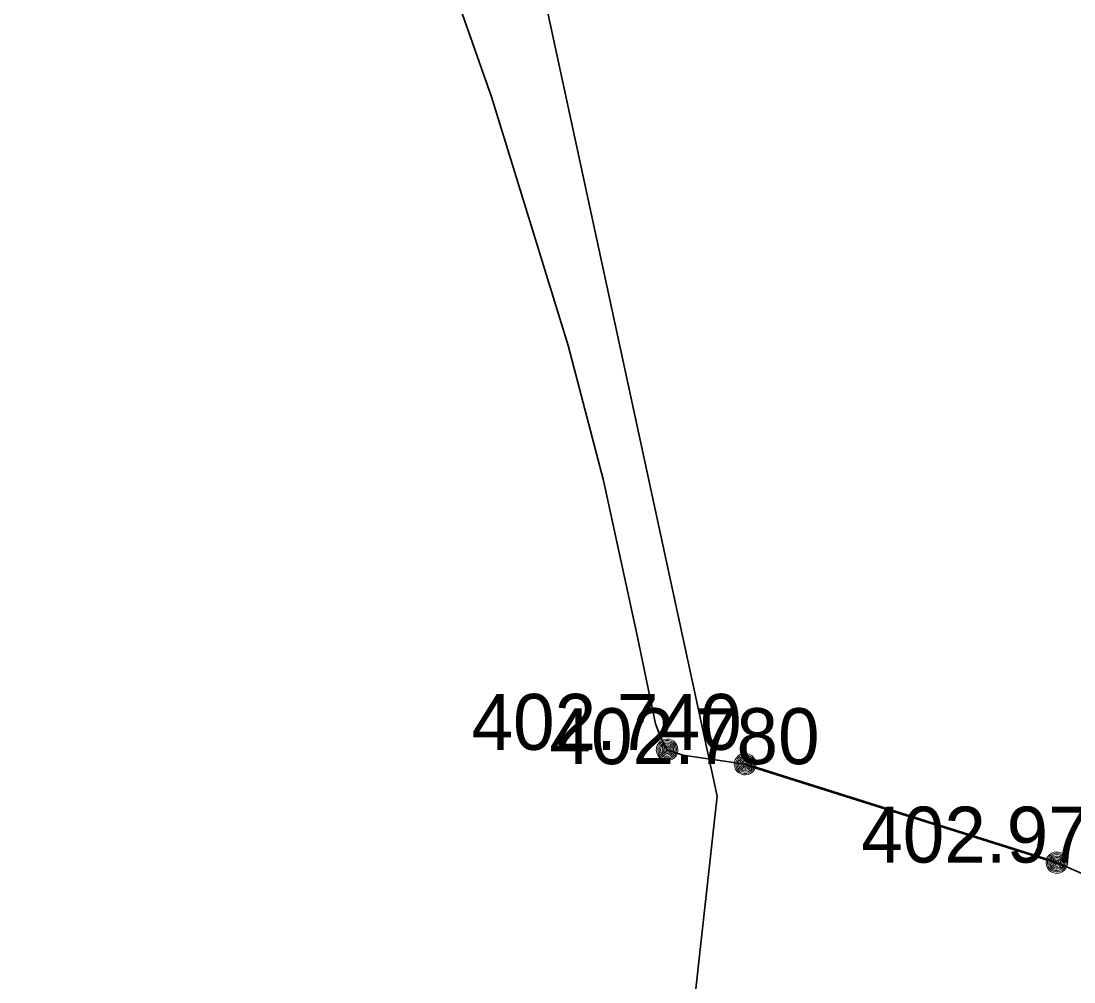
# Model space of a CAD drawing. Extents: x -873619 to -867639, y -1015082 to -1012326.
# Drawn here: x -867993.66 to -867971.06, y -1012799.51 to -1012778.89 of the extents above; entities that cross this region are included whole.
import ezdxf

# ---------------------------------------------------------------- set-up
doc = ezdxf.new("R2010")
doc.units = 0
doc.header["$LTSCALE"] = 0.44
for name, color, linetype, lineweight in [('1', 7, 'Continuous', 13), ('21', 7, 'Continuous', 35), ('26', 7, 'Continuous', 53)]:
    doc.layers.add(name, color=color, linetype=linetype, lineweight=lineweight)

msp = doc.modelspace()

# ---------------------------------------------------------------- linework, layer by layer
at = {"layer": '1', "lineweight": 35}
msp.add_lwpolyline([(-867974.611, -1012725.697), (-867976.949, -1012730.385), (-867980.624, -1012763.205), (-867983.112, -1012775.195), (-867978.719, -1012795.525), (-867979.823, -1012805.464), (-867997.768, -1012829.005), (-868011.042, -1012836.499), (-868058.95, -1012844.4), (-868077.43, -1012833.46), (-868085.171, -1012827.86)], dxfattribs=at)
at = {"layer": '1'}
for points in [[(-867979.561, -1012794.528), (-867979.568, -1012794.476), (-867979.585, -1012794.426), (-867979.614, -1012794.382), (-867979.651, -1012794.345), (-867979.696, -1012794.318), (-867979.745, -1012794.301), (-867979.799, -1012794.297), (-867979.85, -1012794.304), (-867979.899, -1012794.323), (-867979.943, -1012794.352), (-867979.978, -1012794.391), (-867980.005, -1012794.436), (-867980.021, -1012794.487), (-867980.024, -1012794.539), (-867980.016, -1012794.591), (-867979.995, -1012794.64), (-867979.965, -1012794.683), (-867979.926, -1012794.717), (-867979.88, -1012794.743), (-867979.828, -1012794.757), (-867979.776, -1012794.759), (-867979.725, -1012794.749), (-867979.676, -1012794.728), (-867979.634, -1012794.697), (-867979.6, -1012794.656), (-867979.576, -1012794.61), (-867979.563, -1012794.559)], [(-867979.592, -1012794.528), (-867979.598, -1012794.479), (-867979.615, -1012794.433), (-867979.642, -1012794.393), (-867979.679, -1012794.361), (-867979.723, -1012794.339), (-867979.772, -1012794.328), (-867979.821, -1012794.328), (-867979.867, -1012794.341), (-867979.911, -1012794.365), (-867979.946, -1012794.398), (-867979.973, -1012794.439), (-867979.99, -1012794.486), (-867979.994, -1012794.535), (-867979.987, -1012794.583), (-867979.968, -1012794.628), (-867979.938, -1012794.668), (-867979.899, -1012794.699), (-867979.855, -1012794.719), (-867979.808, -1012794.729), (-867979.759, -1012794.727), (-867979.712, -1012794.712), (-867979.669, -1012794.687), (-867979.634, -1012794.653), (-867979.608, -1012794.611), (-867979.595, -1012794.564)], [(-867979.622, -1012794.528), (-867979.627, -1012794.483), (-867979.644, -1012794.441), (-867979.673, -1012794.406), (-867979.708, -1012794.379), (-867979.75, -1012794.362), (-867979.796, -1012794.357), (-867979.84, -1012794.363), (-867979.882, -1012794.382), (-867979.916, -1012794.41), (-867979.943, -1012794.447), (-867979.96, -1012794.489), (-867979.963, -1012794.534), (-867979.956, -1012794.579), (-867979.938, -1012794.62), (-867979.909, -1012794.654), (-867979.872, -1012794.68), (-867979.828, -1012794.696), (-867979.784, -1012794.699), (-867979.739, -1012794.691), (-867979.698, -1012794.671), (-867979.664, -1012794.642), (-867979.639, -1012794.604), (-867979.625, -1012794.561)], [(-867979.652, -1012794.528), (-867979.656, -1012794.487), (-867979.674, -1012794.45), (-867979.701, -1012794.419), (-867979.737, -1012794.398), (-867979.777, -1012794.387), (-867979.818, -1012794.389), (-867979.857, -1012794.402), (-867979.891, -1012794.426), (-867979.916, -1012794.458), (-867979.931, -1012794.496), (-867979.933, -1012794.537), (-867979.926, -1012794.577), (-867979.906, -1012794.613), (-867979.877, -1012794.642), (-867979.84, -1012794.661), (-867979.799, -1012794.669), (-867979.759, -1012794.665), (-867979.72, -1012794.65), (-867979.688, -1012794.624), (-867979.666, -1012794.59), (-867979.652, -1012794.551)], [(-867979.681, -1012794.528), (-867979.686, -1012794.492), (-867979.705, -1012794.46), (-867979.73, -1012794.435), (-867979.764, -1012794.42), (-867979.801, -1012794.417), (-867979.835, -1012794.425), (-867979.867, -1012794.445), (-867979.889, -1012794.473), (-867979.902, -1012794.507), (-867979.902, -1012794.544), (-867979.892, -1012794.579), (-867979.87, -1012794.608), (-867979.84, -1012794.629), (-867979.806, -1012794.639), (-867979.769, -1012794.637), (-867979.735, -1012794.623), (-867979.708, -1012794.6), (-867979.688, -1012794.568), (-867979.681, -1012794.533)], [(-867979.712, -1012794.528), (-867979.717, -1012794.497), (-867979.733, -1012794.471), (-867979.759, -1012794.454), (-867979.789, -1012794.447), (-867979.821, -1012794.451), (-867979.848, -1012794.468), (-867979.865, -1012794.492), (-867979.874, -1012794.523), (-867979.87, -1012794.553), (-867979.855, -1012794.581), (-867979.83, -1012794.6), (-867979.801, -1012794.609), (-867979.769, -1012794.606), (-867979.742, -1012794.592), (-867979.722, -1012794.568), (-867979.712, -1012794.539)], [(-867979.742, -1012794.528), (-867979.747, -1012794.504), (-867979.764, -1012794.486), (-867979.786, -1012794.477), (-867979.811, -1012794.48), (-867979.831, -1012794.494), (-867979.843, -1012794.516), (-867979.843, -1012794.541), (-867979.83, -1012794.562), (-867979.811, -1012794.576), (-867979.786, -1012794.579), (-867979.762, -1012794.57), (-867979.747, -1012794.552)], [(-867979.772, -1012794.528), (-867979.777, -1012794.513), (-867979.791, -1012794.507), (-867979.806, -1012794.511), (-867979.813, -1012794.525), (-867979.809, -1012794.54), (-867979.796, -1012794.549), (-867979.781, -1012794.546), (-867979.772, -1012794.534)], [(-867977.887, -1012794.835), (-867977.894, -1012794.783), (-867977.911, -1012794.733), (-867977.94, -1012794.689), (-867977.977, -1012794.652), (-867978.022, -1012794.625), (-867978.071, -1012794.608), (-867978.125, -1012794.604), (-867978.176, -1012794.611), (-867978.225, -1012794.63), (-867978.269, -1012794.659), (-867978.304, -1012794.698), (-867978.331, -1012794.743), (-867978.347, -1012794.794), (-867978.35, -1012794.846), (-867978.342, -1012794.898), (-867978.321, -1012794.947), (-867978.291, -1012794.99), (-867978.252, -1012795.024), (-867978.206, -1012795.05), (-867978.154, -1012795.064), (-867978.102, -1012795.066), (-867978.051, -1012795.056), (-867978.002, -1012795.035), (-867977.96, -1012795.004), (-867977.926, -1012794.963), (-867977.902, -1012794.917), (-867977.889, -1012794.866)], [(-867977.918, -1012794.835), (-867977.924, -1012794.786), (-867977.941, -1012794.74), (-867977.968, -1012794.7), (-867978.005, -1012794.668), (-867978.049, -1012794.646), (-867978.098, -1012794.635), (-867978.147, -1012794.635), (-867978.193, -1012794.648), (-867978.237, -1012794.672), (-867978.272, -1012794.705), (-867978.299, -1012794.746), (-867978.316, -1012794.793), (-867978.32, -1012794.842), (-867978.313, -1012794.89), (-867978.294, -1012794.935), (-867978.264, -1012794.975), (-867978.225, -1012795.006), (-867978.181, -1012795.026), (-867978.134, -1012795.036), (-867978.085, -1012795.034), (-867978.038, -1012795.019), (-867977.995, -1012794.994), (-867977.96, -1012794.96), (-867977.934, -1012794.918), (-867977.921, -1012794.871)], [(-867977.948, -1012794.835), (-867977.953, -1012794.79), (-867977.97, -1012794.748), (-867977.999, -1012794.713), (-867978.034, -1012794.686), (-867978.076, -1012794.669), (-867978.122, -1012794.664), (-867978.166, -1012794.67), (-867978.208, -1012794.689), (-867978.242, -1012794.717), (-867978.269, -1012794.754), (-867978.286, -1012794.796), (-867978.289, -1012794.841), (-867978.282, -1012794.886), (-867978.264, -1012794.927), (-867978.235, -1012794.961), (-867978.198, -1012794.987), (-867978.154, -1012795.003), (-867978.11, -1012795.006), (-867978.065, -1012794.998), (-867978.024, -1012794.978), (-867977.99, -1012794.949), (-867977.965, -1012794.911), (-867977.951, -1012794.868)], [(-867977.978, -1012794.835), (-867977.982, -1012794.794), (-867978, -1012794.757), (-867978.027, -1012794.726), (-867978.063, -1012794.705), (-867978.103, -1012794.694), (-867978.144, -1012794.696), (-867978.183, -1012794.709), (-867978.217, -1012794.733), (-867978.242, -1012794.765), (-867978.257, -1012794.803), (-867978.259, -1012794.844), (-867978.252, -1012794.884), (-867978.232, -1012794.92), (-867978.203, -1012794.949), (-867978.166, -1012794.968), (-867978.125, -1012794.976), (-867978.085, -1012794.972), (-867978.046, -1012794.957), (-867978.014, -1012794.931), (-867977.992, -1012794.897), (-867977.978, -1012794.858)], [(-867978.007, -1012794.835), (-867978.012, -1012794.799), (-867978.031, -1012794.767), (-867978.056, -1012794.742), (-867978.09, -1012794.727), (-867978.127, -1012794.724), (-867978.161, -1012794.732), (-867978.193, -1012794.752), (-867978.215, -1012794.78), (-867978.228, -1012794.814), (-867978.228, -1012794.851), (-867978.218, -1012794.886), (-867978.196, -1012794.915), (-867978.166, -1012794.936), (-867978.132, -1012794.946), (-867978.095, -1012794.944), (-867978.061, -1012794.93), (-867978.034, -1012794.907), (-867978.014, -1012794.875), (-867978.007, -1012794.84)], [(-867978.038, -1012794.835), (-867978.043, -1012794.804), (-867978.059, -1012794.778), (-867978.085, -1012794.761), (-867978.115, -1012794.754), (-867978.147, -1012794.758), (-867978.174, -1012794.775), (-867978.191, -1012794.799), (-867978.2, -1012794.83), (-867978.196, -1012794.86), (-867978.181, -1012794.888), (-867978.156, -1012794.907), (-867978.127, -1012794.916), (-867978.095, -1012794.913), (-867978.068, -1012794.899), (-867978.048, -1012794.875), (-867978.038, -1012794.846)], [(-867978.068, -1012794.835), (-867978.073, -1012794.811), (-867978.09, -1012794.793), (-867978.112, -1012794.784), (-867978.137, -1012794.787), (-867978.157, -1012794.801), (-867978.169, -1012794.823), (-867978.169, -1012794.848), (-867978.156, -1012794.869), (-867978.137, -1012794.883), (-867978.112, -1012794.886), (-867978.088, -1012794.877), (-867978.073, -1012794.859)], [(-867978.098, -1012794.835), (-867978.103, -1012794.82), (-867978.117, -1012794.814), (-867978.132, -1012794.818), (-867978.139, -1012794.832), (-867978.136, -1012794.847), (-867978.122, -1012794.856), (-867978.107, -1012794.853), (-867978.098, -1012794.841)], [(-867971.195, -1012796.948), (-867971.201, -1012796.896), (-867971.218, -1012796.846), (-867971.247, -1012796.802), (-867971.284, -1012796.765), (-867971.329, -1012796.738), (-867971.379, -1012796.721), (-867971.432, -1012796.717), (-867971.483, -1012796.724), (-867971.532, -1012796.743), (-867971.576, -1012796.772), (-867971.612, -1012796.811), (-867971.638, -1012796.856), (-867971.654, -1012796.907), (-867971.657, -1012796.959), (-867971.649, -1012797.011), (-867971.629, -1012797.06), (-867971.598, -1012797.103), (-867971.559, -1012797.137), (-867971.513, -1012797.163), (-867971.462, -1012797.177), (-867971.409, -1012797.179), (-867971.358, -1012797.169), (-867971.309, -1012797.148), (-867971.267, -1012797.117), (-867971.233, -1012797.076), (-867971.209, -1012797.03), (-867971.196, -1012796.979)], [(-867971.225, -1012796.948), (-867971.231, -1012796.899), (-867971.248, -1012796.853), (-867971.276, -1012796.813), (-867971.313, -1012796.781), (-867971.357, -1012796.759), (-867971.405, -1012796.748), (-867971.454, -1012796.748), (-867971.5, -1012796.761), (-867971.544, -1012796.785), (-867971.58, -1012796.818), (-867971.607, -1012796.859), (-867971.623, -1012796.906), (-867971.627, -1012796.955), (-867971.62, -1012797.003), (-867971.601, -1012797.048), (-867971.571, -1012797.088), (-867971.532, -1012797.119), (-867971.489, -1012797.139), (-867971.441, -1012797.149), (-867971.392, -1012797.147), (-867971.345, -1012797.132), (-867971.302, -1012797.107), (-867971.267, -1012797.073), (-867971.242, -1012797.031), (-867971.228, -1012796.984)], [(-867971.255, -1012796.948), (-867971.261, -1012796.903), (-867971.277, -1012796.861), (-867971.306, -1012796.826), (-867971.342, -1012796.799), (-867971.384, -1012796.782), (-867971.429, -1012796.777), (-867971.473, -1012796.783), (-867971.515, -1012796.802), (-867971.549, -1012796.83), (-867971.576, -1012796.867), (-867971.593, -1012796.909), (-867971.597, -1012796.954), (-867971.59, -1012796.999), (-867971.571, -1012797.04), (-867971.542, -1012797.074), (-867971.505, -1012797.1), (-867971.462, -1012797.116), (-867971.417, -1012797.119), (-867971.372, -1012797.111), (-867971.331, -1012797.091), (-867971.298, -1012797.062), (-867971.272, -1012797.024), (-867971.258, -1012796.981)], [(-867971.285, -1012796.948), (-867971.289, -1012796.907), (-867971.308, -1012796.87), (-867971.335, -1012796.839), (-867971.37, -1012796.818), (-867971.41, -1012796.807), (-867971.451, -1012796.809), (-867971.49, -1012796.822), (-867971.524, -1012796.846), (-867971.549, -1012796.878), (-867971.564, -1012796.916), (-867971.566, -1012796.957), (-867971.559, -1012796.997), (-867971.539, -1012797.033), (-867971.51, -1012797.062), (-867971.473, -1012797.081), (-867971.433, -1012797.089), (-867971.392, -1012797.085), (-867971.353, -1012797.07), (-867971.321, -1012797.044), (-867971.299, -1012797.01), (-867971.286, -1012796.971)], [(-867971.315, -1012796.948), (-867971.32, -1012796.912), (-867971.338, -1012796.88), (-867971.364, -1012796.855), (-867971.397, -1012796.84), (-867971.434, -1012796.837), (-867971.468, -1012796.845), (-867971.5, -1012796.865), (-867971.522, -1012796.893), (-867971.536, -1012796.927), (-867971.536, -1012796.964), (-867971.525, -1012796.999), (-867971.504, -1012797.028), (-867971.473, -1012797.049), (-867971.439, -1012797.059), (-867971.402, -1012797.057), (-867971.368, -1012797.043), (-867971.341, -1012797.02), (-867971.321, -1012796.988), (-867971.315, -1012796.953)], [(-867971.345, -1012796.948), (-867971.35, -1012796.917), (-867971.367, -1012796.891), (-867971.392, -1012796.874), (-867971.423, -1012796.867), (-867971.454, -1012796.871), (-867971.481, -1012796.888), (-867971.499, -1012796.912), (-867971.507, -1012796.943), (-867971.503, -1012796.973), (-867971.488, -1012797.001), (-867971.463, -1012797.02), (-867971.434, -1012797.029), (-867971.402, -1012797.026), (-867971.375, -1012797.012), (-867971.355, -1012796.988), (-867971.345, -1012796.959)], [(-867971.375, -1012796.948), (-867971.38, -1012796.924), (-867971.397, -1012796.906), (-867971.419, -1012796.897), (-867971.444, -1012796.9), (-867971.465, -1012796.914), (-867971.476, -1012796.936), (-867971.476, -1012796.961), (-867971.463, -1012796.982), (-867971.444, -1012796.996), (-867971.419, -1012796.999), (-867971.396, -1012796.99), (-867971.38, -1012796.972)], [(-867971.405, -1012796.948), (-867971.41, -1012796.933), (-867971.424, -1012796.927), (-867971.44, -1012796.931), (-867971.446, -1012796.945), (-867971.443, -1012796.96), (-867971.429, -1012796.969), (-867971.414, -1012796.966), (-867971.405, -1012796.954)]]:
    msp.add_lwpolyline(points, close=True, dxfattribs=at)
at = {"layer": '21'}
msp.add_lwpolyline([(-867985.041, -1012776.301), (-867983.561, -1012780.516), (-867981.915, -1012785.847), (-867981.161, -1012788.75), (-867980.435, -1012792.072), (-867980.045, -1012793.97), (-867979.933, -1012794.249), (-867979.793, -1012794.528), (-867979.458, -1012794.64), (-867978.119, -1012794.835), (-867971.426, -1012796.948), (-867970.889, -1012797.18)], dxfattribs=at)
at = {"layer": '26'}
msp.add_line((-867978.119, -1012794.835), (-867971.426, -1012796.948), dxfattribs=at)

# ---------------------------------------------------------------- texts
at = {"layer": '1'}
for s, p in [('402.740 ', (-867983.993, -1012794.528)), ('402.780 ', (-867982.319, -1012794.835)), ('402.970 ', (-867975.626, -1012796.948))]:
    msp.add_text(s, height=1.2, dxfattribs=at).set_placement(p)

doc.saveas('drawing.dxf')
